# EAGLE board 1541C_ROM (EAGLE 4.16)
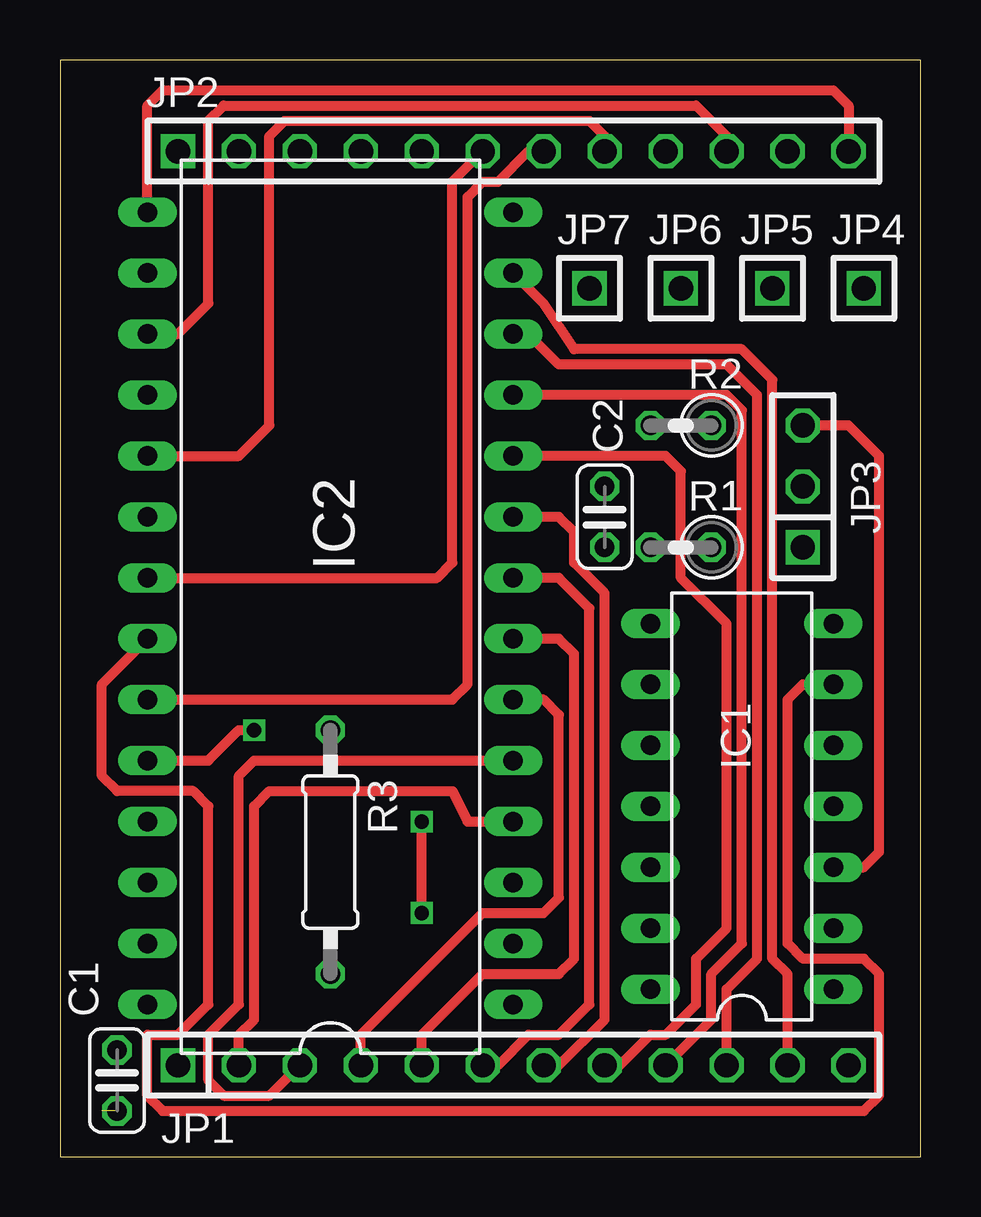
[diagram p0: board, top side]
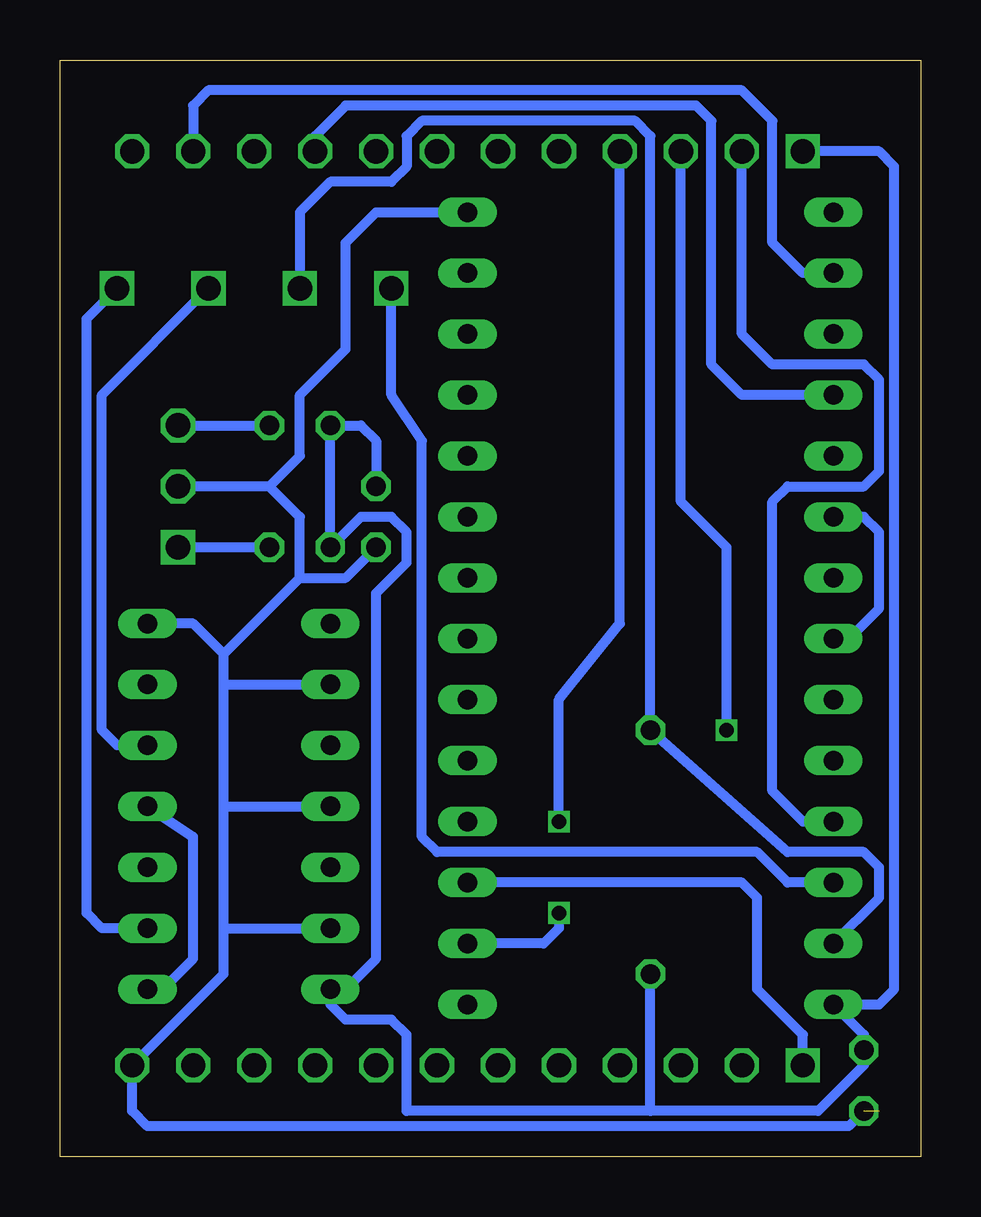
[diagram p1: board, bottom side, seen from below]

Size 35.87 x 45.71 mm. Coordinates in mm from the lower left corner, seen from the top.
Outline: 0,0 35.87,0 35.87,45.71 0,45.71 0,0
Copper layers (1*16): Top 0.035mm / dielectric 1.5mm / Bottom 0.035mm
Design rules "PCB-POOL": minimum track width 6mil, minimum drill 12mil, track to track 6mil, track to pad 6mil, pad to pad 6mil, via to via 6mil, smd to smd 6mil, copper to edge 20mil, drill to drill 8mil, minimum pad ring 8mil, minimum via ring 6mil, stop-mask expansion 3mil, vias tented up to drill 0mil, thermal gap 8mil

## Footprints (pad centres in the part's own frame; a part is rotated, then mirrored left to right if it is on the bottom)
C025-024X044 = drill 0.813 octagon: 1 -1.27,0; 2 1.27,0
DIL14 = drill 0.813 long: 1 -7.62,-3.81; 2 -5.08,-3.81; 3 -2.54,-3.81; 4 0,-3.81; 5 2.54,-3.81; 6 5.08,-3.81; 7 7.62,-3.81; 8 7.62,3.81; 9 5.08,3.81; 10 2.54,3.81; 11 0,3.81; 12 -2.54,3.81; 13 -5.08,3.81; 14 -7.62,3.81
DIL28-6 = drill 0.813 long: 1 -16.51,-7.62; 2 -13.97,-7.62; 3 -11.43,-7.62; 4 -8.89,-7.62; 5 -6.35,-7.62; 6 -3.81,-7.62; 7 -1.27,-7.62; 8 1.27,-7.62; 9 3.81,-7.62; 10 6.35,-7.62; 11 8.89,-7.62; 12 11.43,-7.62; 13 13.97,-7.62; 14 16.51,-7.62; 15 16.51,7.62; 16 13.97,7.62; 17 11.43,7.62; 18 8.89,7.62; 19 6.35,7.62; 20 3.81,7.62; 21 1.27,7.62; 22 -1.27,7.62; 23 -3.81,7.62; 24 -6.35,7.62; 25 -8.89,7.62; 26 -11.43,7.62; 27 -13.97,7.62; 28 -16.51,7.62
1X12 = drill 1.016 square: 1 -13.97,0 | drill 1.016 octagon: 2 -11.43,0; 3 -8.89,0; 4 -6.35,0; 5 -3.81,0; 6 -1.27,0; 7 1.27,0; 8 3.81,0; 9 6.35,0; 10 8.89,0; 11 11.43,0; 12 13.97,0
1X03 = drill 1.016 square: 1 -2.54,0 | drill 1.016 octagon: 2 0,0; 3 2.54,0
1X01 = drill 1.016 square: 1 0,0
0207/2V = drill 0.813 octagon: 1 -1.27,0; 2 1.27,0
0207/10 = drill 0.813 octagon: 1 -5.08,0; 2 5.08,0

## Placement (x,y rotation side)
C1  100n  [C025-024X044]  2.38,3.17 90 top
C2  100n  [C025-024X044]  22.7,26.66 270 top
IC1  4069N  [DIL14]  28.41,14.6 90 top
IC2  27C256P  [DIL28-6]  11.27,22.86 90 top
JP1  [1X12]  18.88,3.8 0 top
JP2  [1X12]  18.88,41.91 0 top
JP3  [1X03]  30.95,27.93 90 top
JP4  [1X01]  33.49,36.19 0 top
JP5  [1X01]  29.68,36.19 0 top
JP6  [1X01]  25.87,36.19 0 top
JP7  [1X01]  22.06,36.19 0 top
R1  150R  [0207/2V]  25.87,25.39 180 top
R2  47k  [0207/2V]  25.87,30.47 180 top
R3  4,7k  [0207/10]  11.27,12.7 270 top

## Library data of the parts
C1 C2 R1-R3 = rcl
IC1 = 40xx
IC2 = microchip
JP1-JP7 = pinhead

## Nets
+5V: C1.2 C2.1 IC1.14 IC2.28 JP2.1 R1.2 R2.2 R3.2
GND: C1.1 C2.2 IC1.7 IC1.9 IC1.11 IC1.13 IC2.14 JP1.12 JP3.2
N$1: IC1.6 IC2.20 IC2.22
N$2: IC2.27 JP6.1 R3.1
N$3: IC1.5 JP5.1
N$4: IC1.3 JP3.3 R2.1
N$5: JP3.1 R1.1
N$6: IC1.1 IC1.4
N$7: IC1.2 JP4.1
N$8: IC2.10 JP1.8
N$9: IC2.9 JP1.7
N$10: IC2.8 JP1.6
N$11: IC2.7 JP1.5
N$12: IC2.6 JP1.4
N$13: IC2.5 JP1.3
N$14: IC2.4 JP1.2
N$15: IC2.3 JP1.1
N$17: IC2.11 JP1.9
N$18: IC2.12 JP1.10
N$19: IC2.25 JP2.2
N$20: IC2.24 JP2.3
N$21: IC2.2 JP2.4
N$22: IC2.21 JP2.6
N$23: IC2.23 JP2.7
N$24: IC2.26 JP7.1
N$25: IC2.13 JP1.11
N$26: IC2.19 JP2.8
N$27: IC2.18 JP2.9
N$28: IC2.17 JP2.10
N$29: IC2.16 JP2.11
N$30: IC2.15 JP2.12

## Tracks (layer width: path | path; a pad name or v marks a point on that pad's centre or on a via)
+5V
  Bottom 0.406: JP2.1 1.74,41.91 1.1,41.27 1.1,6.98 1.74,6.34 IC2.28 2.38,5.08 C1.2 2.38,3.8 4.28,1.9 11.27,1.9 | 11.27,1.9 21.42,1.9 21.42,5.08 22.06,5.71 23.96,5.71 24.6,6.34 IC1.14 23.96,6.98 22.7,8.25 22.7,23.49 21.42,24.76 21.42,26.03 22.06,26.66 23.33,26.66 R1.2 R2.2 23.33,30.47 22.7,29.84 C2.1 | 11.27,1.9 R3.2
GND  (1 unrouted)
  Bottom 0.406: C1.1 3.01,1.27 32.22,1.27 32.85,1.9 JP1.12 29.04,7.62 29.04,9.52 | 29.04,9.52 IC1.13 | IC1.7 30.31,22.22 29.04,20.95 | 29.04,9.52 29.04,14.6 | 29.04,14.6 29.04,19.68 | 29.04,19.68 29.04,20.95 | 29.04,19.68 IC1.9 | 29.04,14.6 IC1.11 | 27.14,27.93 JP3.2 | 27.14,27.93 25.87,26.66 25.87,24.12 | 29.04,20.95 25.87,24.12 | IC2.14 22.7,39.37 23.96,38.1 23.96,33.65 25.87,31.74 25.87,29.2 27.14,27.93 | C2.2 23.96,24.12 25.87,24.12
N$1
  Top 0.406: IC1.6 30.95,19.68 30.31,19.04 30.31,8.89 30.95,8.25 33.49,8.25 34.12,7.62 34.12,2.54 33.49,1.9 4.28,1.9 3.64,2.54 3.64,5.08 4.92,5.08 6.18,6.34 6.18,14.6 5.55,15.24 2.38,15.24 1.74,15.87 1.74,19.68 IC2.22
  Bottom 0.406: IC2.22 3.01,21.58 1.74,22.86 1.74,26.03 2.38,26.66 IC2.20
N$2
  Bottom 0.406: IC2.27 1.74,10.79 1.74,12.06 2.38,12.7 5.55,12.7 R3.1 11.27,42.54 11.9,43.18 20.79,43.18 21.42,42.54 21.42,41.27 22.06,40.64 24.6,40.64 25.87,39.37 JP6.1
N$3
  Bottom 0.406: JP5.1 34.12,31.74 34.12,17.77 33.49,17.14 IC1.5
N$4
  Top 0.406: IC1.3 33.49,12.06 34.12,12.7 34.12,29.2 32.85,30.47 JP3.3
  Bottom 0.406: JP3.3 R2.1
N$5
  Bottom 0.406: R1.1 JP3.1
N$6
  Bottom 0.406: IC1.1 31.58,6.98 30.31,8.25 30.31,13.33 IC1.4
N$7
  Bottom 0.406: JP4.1 34.76,34.92 34.76,10.16 34.12,9.52 IC1.2
N$8
  Top 0.406: JP1.8 23.33,3.8 24.6,5.08 25.23,5.08 26.5,6.34 26.5,8.25 27.77,9.52 27.77,22.22 25.87,24.12 25.87,28.57 25.23,29.2 IC2.10
N$9
  Top 0.406: JP1.7 20.79,3.8 22.7,5.71 22.7,23.49 21.42,24.76 21.42,26.03 20.79,26.66 IC2.9
N$10
  Top 0.406: JP1.6 18.25,3.8 19.52,5.08 20.79,5.08 22.06,6.34 22.06,22.86 20.79,24.12 IC2.8
N$11
  Top 0.406: JP1.5 15.08,5.08 17.61,7.62 20.79,7.62 21.42,8.25 21.42,20.95 20.79,21.58 IC2.7
N$12
  Top 0.406: JP1.4 12.54,5.08 17.61,10.16 20.15,10.16 20.79,10.79 20.79,18.41 20.15,19.04 IC2.6
N$13
  Top 0.406: JP1.3 8.73,2.54 6.82,2.54 6.18,3.17 6.18,5.08 7.46,6.34 7.46,15.87 8.09,16.5 IC2.5
N$14
  Top 0.406: JP1.2 7.46,5.08 8.09,5.71 8.09,14.6 8.73,15.24 16.34,15.24 16.98,13.97 IC2.4
N$15
  Bottom 0.406: JP1.1 4.92,5.08 6.82,6.98 6.82,10.79 7.46,11.43 IC2.3
N$17
  Top 0.406: JP1.9 27.14,5.71 27.14,7.62 28.41,8.89 28.41,31.11 27.77,31.74 IC2.11
N$18
  Top 0.406: JP1.10 27.77,6.98 29.04,8.25 29.04,31.74 27.77,33.02 20.79,33.02 19.52,34.29 IC2.12
N$19
  Bottom 0.406: IC2.25 4.92,13.97 6.18,15.24 6.18,27.3 5.55,27.93 2.38,27.93 1.74,28.57 1.74,32.38 2.38,33.02 6.18,33.02 7.46,34.29 JP2.2
N$20  (via drill 0.6)
  Top 0.406: IC2.24 6.18,16.5 7.46,17.77 v8.09,17.77
  Bottom 0.406: v8.09,17.77 8.09,25.39 10,27.3 JP2.3
N$21  (via drill 0.6)
  Top 0.406: v15.08,10.16 v15.08,13.97
  Bottom 0.406: IC2.2 15.71,8.89 15.08,9.52 v15.08,10.16 | v15.08,13.97 15.08,19.04 12.54,22.22 JP2.4
N$22
  Top 0.406: JP2.6 16.34,40.64 16.34,24.76 15.71,24.12 IC2.21
N$23
  Top 0.406: JP2.7 19.52,41.91 18.25,40.64 17.61,40.64 16.98,40 16.98,19.68 16.34,19.04 IC2.23
N$24
  Bottom 0.406: JP7.1 22.06,31.74 20.79,29.84 20.79,13.33 20.15,12.7 6.82,12.7 5.55,11.43 IC2.26
N$25
  Top 0.406: JP1.11 30.31,7.62 29.68,8.25 29.68,32.38 28.41,33.65 21.42,33.65 20.15,35.55 IC2.13
N$26
  Top 0.406: JP2.8 22.7,42.54 22.06,43.18 9.36,43.18 8.73,42.54 8.73,30.47 7.46,29.2 IC2.19
N$27
  Bottom 0.406: JP2.9 25.23,42.54 23.96,43.81 9.36,43.81 8.73,43.18 8.73,33.02 7.46,31.74 IC2.18
N$28
  Top 0.406: JP2.10 27.77,42.54 26.5,43.81 6.82,43.81 6.18,43.18 6.18,35.55 4.92,34.29 IC2.17
N$29
  Bottom 0.406: JP2.11 30.31,43.81 29.68,44.45 7.46,44.45 6.18,43.18 6.18,38.1 4.92,36.83 IC2.16
N$30
  Top 0.406: JP2.12 32.85,43.81 32.22,44.45 4.28,44.45 3.64,43.81 IC2.15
